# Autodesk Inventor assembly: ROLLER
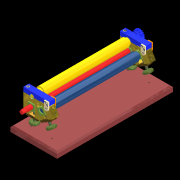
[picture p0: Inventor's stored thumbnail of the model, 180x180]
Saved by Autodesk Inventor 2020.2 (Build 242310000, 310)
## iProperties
Manager: ASSEMBLY
Company: 4
Created: 2020-10
Part Number: ROLLER
Document SubType Name: Assembly
Designer: Apardo
Project: PLATE ROLLING MACHINE
Cost Center: 1
Description: ROLLER
Engineer: STEEL MEATL
Stock Number: 1
Engr Approved By: D. JAEGER
Author: Apardo
Revision Number: 1.0
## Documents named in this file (20)
- C:\Users\Apardo\Documents\Proyectos\Dietrich\Proyecto 1\PLATE ROLLING MACHINE\ROLLER.iam
- C:\Users\Apardo\Documents\Proyectos\Dietrich\Proyecto 1\PLATE ROLLING MACHINE\base plate.ipt
- C:\Users\Apardo\Documents\Proyectos\Dietrich\Proyecto 1\PLATE ROLLING MACHINE\hinge.ipt
- C:\Users\Apardo\Documents\Proyectos\Dietrich\Proyecto 1\PLATE ROLLING MACHINE\hinge seat A.ipt
- C:\Users\Apardo\Documents\Proyectos\Dietrich\Proyecto 1\PLATE ROLLING MACHINE\hinge seat B.ipt
- C:\Users\Apardo\Documents\Proyectos\Dietrich\Proyecto 1\PLATE ROLLING MACHINE\plate.ipt
- C:\Users\Apardo\Documents\Proyectos\Dietrich\Proyecto 1\PLATE ROLLING MACHINE\position 2.ipt
- C:\Users\Apardo\Documents\Proyectos\Dietrich\Proyecto 1\PLATE ROLLING MACHINE\position 8.ipt
- C:\Users\Apardo\Documents\Proyectos\Dietrich\Proyecto 1\PLATE ROLLING MACHINE\pressure screw.ipt
- C:\Users\Apardo\Documents\Proyectos\Dietrich\Proyecto 1\PLATE ROLLING MACHINE\rollerA.ipt
- C:\Users\Apardo\Documents\Proyectos\Dietrich\Proyecto 1\PLATE ROLLING MACHINE\rollerB.ipt
- C:\Users\Apardo\Documents\Proyectos\Dietrich\Proyecto 1\PLATE ROLLING MACHINE\rollerC.ipt
- C:\Users\Apardo\Documents\Proyectos\Dietrich\Proyecto 1\PLATE ROLLING MACHINE\bearingA.ipt
- C:\Users\Apardo\Documents\Proyectos\Dietrich\Proyecto 1\PLATE ROLLING MACHINE\bearingB.ipt
- C:\Users\Apardo\Documents\Proyectos\Dietrich\Proyecto 1\PLATE ROLLING MACHINE\CRADLE.ipt
- C:\Users\Apardo\Documents\Proyectos\Dietrich\Proyecto 1\PLATE ROLLING MACHINE\gear.ipt
- C:\Users\Apardo\Documents\Inventor\Content Center Files\R2020\en-US\ASME ANSI B18.3.5M(2)\ASME_ANSI B18.3.5M - M5x14(2).ipt
- C:\Users\Apardo\Documents\Inventor\Content Center Files\R2020\en-US\ASME ANSI B18.3.5M(2)\ASME_ANSI B18.3.5M - M4x10(2).ipt
- C:\Users\Apardo\Documents\Inventor\Content Center Files\R2020\en-US\ANSI B18.3.1M(1)\ANSI B18.3.1M - M6x1 x 20(2).ipt
- C:\Users\Apardo\Documents\Inventor\Content Center Files\R2020\en-US\IFI 512-C\IFI 512-C - 6 x 28280,5.ipt
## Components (50 placed, 19 different names)
1. base plate:1
2. hinge:1 — Insert:5, Mate:5, Insert:6, Mate:6, Insert:19, Flush:3, Insert:44
3. hinge:2 — Insert:3, Mate:3, Insert:4, Mate:4, Insert:18, Insert:43
4. hinge seat A:1 — Insert:3, Mate:3, Insert:39, Insert:40, Insert:53
5. hinge seat B:1 — Insert:4, Mate:4, Insert:45, Insert:46
6. hinge seat A:2 — Insert:5, Mate:5, Insert:47, Insert:48, Insert:54
7. hinge seat B:2 — Insert:6, Mate:6, Insert:41, Insert:42
8. plate:1 — Insert:13, Mate:17, Mate:23, Insert:36, Insert:37
9. plate:2 — Insert:12, Mate:16, Mate:22, Insert:35, Insert:38
10. plate:3 — Insert:11, Mate:15, Insert:23, Insert:31, Insert:32
11. plate:4 — Insert:10, Mate:14, Insert:22, Insert:29, Insert:30
12. position 2:1 — Mate:9, Mate:10, Insert:10, Mate:14, Insert:11, Mate:15, Mate:18, Insert:18, Insert:20
13. position 2:2 — Mate:11, Mate:12, Insert:12, Mate:16, Insert:13, Mate:17, Mate:19, Insert:19, Flush:3
14. position 8:1 — Mate:9, Mate:10, Mate:13, Flush:1
15. position 8:2 — Mate:11, Mate:12, Mate:13, Insert:9, Flush:2
16. position 8:3 — Mate:18, Flush:1, Mate:20, Insert:14
17. position 8:4 — Mate:19, Flush:2, Mate:20
18. pressure screw:1 — Insert:23, Flush:5
19. pressure screw:2 — Insert:22, Flush:4
20. pressure screw:3 — Mate:22, Flush:4
21. pressure screw:4 — Mate:23, Flush:5
22. rollerA:1 — Insert:9
23. rollerB:1 — Insert:15, Insert:16, Insert:20, Tangent:1, Insert:24, Mate:24
24. rollerC:1 — Insert:14, Tangent:1, Insert:25, Mate:25, Insert:27
25. bearingA:1 — Insert:16, Insert:26
26. bearingB:1 — Insert:15
27. CRADLE:1 — Insert:25, Mate:25, Mate:26
28. CRADLE:2 — Insert:24, Mate:24, Mate:27
29. gear:1 — Insert:26, Mate:27
30. gear:2 — Insert:27, Mate:26
31. Broached Hexagon Socket Flat Countersunk Head Cap Screws - Metric M5x14:1 — Insert:32
32. Broached Hexagon Socket Flat Countersunk Head Cap Screws - Metric M5x14:2 — Insert:30
33. Broached Hexagon Socket Flat Countersunk Head Cap Screws - Metric M5x14:3 — Insert:38
34. Broached Hexagon Socket Flat Countersunk Head Cap Screws - Metric M5x14:4 — Insert:31
35. Broached Hexagon Socket Flat Countersunk Head Cap Screws - Metric M5x14:6 — Insert:29
36. Broached Hexagon Socket Flat Countersunk Head Cap Screws - Metric M5x14:7 — Insert:35
37. Broached Hexagon Socket Flat Countersunk Head Cap Screws - Metric M5x14:8 — Insert:36
38. Broached Hexagon Socket Flat Countersunk Head Cap Screws - Metric M5x14:9 — Insert:37
39. Broached Hexagon Socket Flat Countersunk Head Cap Screws - Metric M4x10:1 — Insert:41
40. Broached Hexagon Socket Flat Countersunk Head Cap Screws - Metric M4x10:2 — Insert:42
41. Broached Hexagon Socket Flat Countersunk Head Cap Screws - Metric M4x10:3 — Insert:39
42. Broached Hexagon Socket Flat Countersunk Head Cap Screws - Metric M4x10:4 — Insert:40
43. Broached Hexagon Socket Flat Countersunk Head Cap Screws - Metric M4x10:5 — Insert:47
44. Broached Hexagon Socket Flat Countersunk Head Cap Screws - Metric M4x10:6 — Insert:48
45. Broached Hexagon Socket Flat Countersunk Head Cap Screws - Metric M4x10:7 — Insert:46
46. Broached Hexagon Socket Flat Countersunk Head Cap Screws - Metric M4x10:8 — Insert:45
47. Broached Socket Head Cap Screw - Metric M6x1 x 20:1 — Insert:44
48. Broached Socket Head Cap Screw - Metric M6x1 x 20:2 — Insert:43
49. Pin - Coiled Spring (Metric) 6 x 28:1 — Insert:54
50. Pin - Coiled Spring (Metric) 6 x 28:2 — Insert:53
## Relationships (69: Insert 41, Mate 22, Flush 5, Tangent 1)
- Insert:3: hinge:2 ↔ hinge seat A:1
- Mate:3: hinge:2 ↔ hinge seat A:1
- Insert:4: hinge:2 ↔ hinge seat B:1
- Mate:4: hinge:2 ↔ hinge seat B:1
- Insert:5: hinge:1 ↔ hinge seat A:2
- Mate:5: hinge:1 ↔ hinge seat A:2
- Insert:6: hinge:1 ↔ hinge seat B:2
- Mate:6: hinge:1 ↔ hinge seat B:2
- Mate:9: position 2:1 ↔ position 8:1
- Mate:10: position 2:1 ↔ position 8:1
- Mate:11: position 2:2 ↔ position 8:2
- Mate:12: position 2:2 ↔ position 8:2
- Mate:13: position 8:1 ↔ position 8:2
- Insert:9: position 8:2 ↔ rollerA:1
- Insert:10: plate:4 ↔ position 2:1
- Mate:14: plate:4 ↔ position 2:1
- Insert:11: plate:3 ↔ position 2:1
- Mate:15: plate:3 ↔ position 2:1
- Insert:12: plate:2 ↔ position 2:2
- Mate:16: plate:2 ↔ position 2:2
- Insert:13: plate:1 ↔ position 2:2
- Mate:17: plate:1 ↔ position 2:2
- Mate:18: position 2:1 ↔ position 8:3
- Flush:1: position 8:1 ↔ position 8:3
- Mate:19: position 2:2 ↔ position 8:4
- Flush:2: position 8:2 ↔ position 8:4
- Mate:20: position 8:3 ↔ position 8:4
- Insert:14: position 8:3 ↔ rollerC:1
- Insert:15: rollerB:1 ↔ bearingB:1
- Insert:16: rollerB:1 ↔ bearingA:1
- Insert:18: hinge:2 ↔ position 2:1
- Insert:19: hinge:1 ↔ position 2:2
- Flush:3: hinge:1 ↔ position 2:2
- Insert:20: position 2:1 ↔ rollerB:1
- Tangent:1: rollerB:1 ↔ rollerC:1
- Insert:22: plate:4 ↔ pressure screw:2
- Insert:23: plate:3 ↔ pressure screw:1
- Mate:22: plate:2 ↔ pressure screw:3
- Flush:4: pressure screw:2 ↔ pressure screw:3
- Mate:23: plate:1 ↔ pressure screw:4
- Flush:5: pressure screw:1 ↔ pressure screw:4
- Insert:24: rollerB:1 ↔ CRADLE:2
- Mate:24: rollerB:1 ↔ CRADLE:2
- Insert:25: rollerC:1 ↔ CRADLE:1
- Mate:25: rollerC:1 ↔ CRADLE:1
- Insert:26: bearingA:1 ↔ gear:1
- Insert:27: rollerC:1 ↔ gear:2
- Mate:26: CRADLE:1 ↔ gear:2
- Mate:27: CRADLE:2 ↔ gear:1
- Insert:29: plate:4 ↔ Broached Hexagon Socket Flat Countersunk Head Cap Screws - Metric M5x14:6
- Insert:30: plate:4 ↔ Broached Hexagon Socket Flat Countersunk Head Cap Screws - Metric M5x14:2
- Insert:31: plate:3 ↔ Broached Hexagon Socket Flat Countersunk Head Cap Screws - Metric M5x14:4
- Insert:32: plate:3 ↔ Broached Hexagon Socket Flat Countersunk Head Cap Screws - Metric M5x14:1
- Insert:35: plate:2 ↔ Broached Hexagon Socket Flat Countersunk Head Cap Screws - Metric M5x14:7
- Insert:36: plate:1 ↔ Broached Hexagon Socket Flat Countersunk Head Cap Screws - Metric M5x14:8
- Insert:37: plate:1 ↔ Broached Hexagon Socket Flat Countersunk Head Cap Screws - Metric M5x14:9
- Insert:38: plate:2 ↔ Broached Hexagon Socket Flat Countersunk Head Cap Screws - Metric M5x14:3
- Insert:39: hinge seat A:1 ↔ Broached Hexagon Socket Flat Countersunk Head Cap Screws - Metric M4x10:3
- Insert:40: hinge seat A:1 ↔ Broached Hexagon Socket Flat Countersunk Head Cap Screws - Metric M4x10:4
- Insert:41: hinge seat B:2 ↔ Broached Hexagon Socket Flat Countersunk Head Cap Screws - Metric M4x10:1
- Insert:42: hinge seat B:2 ↔ Broached Hexagon Socket Flat Countersunk Head Cap Screws - Metric M4x10:2
- Insert:43: hinge:2 ↔ Broached Socket Head Cap Screw - Metric M6x1 x 20:2
- Insert:44: hinge:1 ↔ Broached Socket Head Cap Screw - Metric M6x1 x 20:1
- Insert:45: hinge seat B:1 ↔ Broached Hexagon Socket Flat Countersunk Head Cap Screws - Metric M4x10:8
- Insert:46: hinge seat B:1 ↔ Broached Hexagon Socket Flat Countersunk Head Cap Screws - Metric M4x10:7
- Insert:47: hinge seat A:2 ↔ Broached Hexagon Socket Flat Countersunk Head Cap Screws - Metric M4x10:5
- Insert:48: hinge seat A:2 ↔ Broached Hexagon Socket Flat Countersunk Head Cap Screws - Metric M4x10:6
- Insert:53: hinge seat A:1 ↔ Pin - Coiled Spring (Metric) 6 x 28:2
- Insert:54: hinge seat A:2 ↔ Pin - Coiled Spring (Metric) 6 x 28:1
